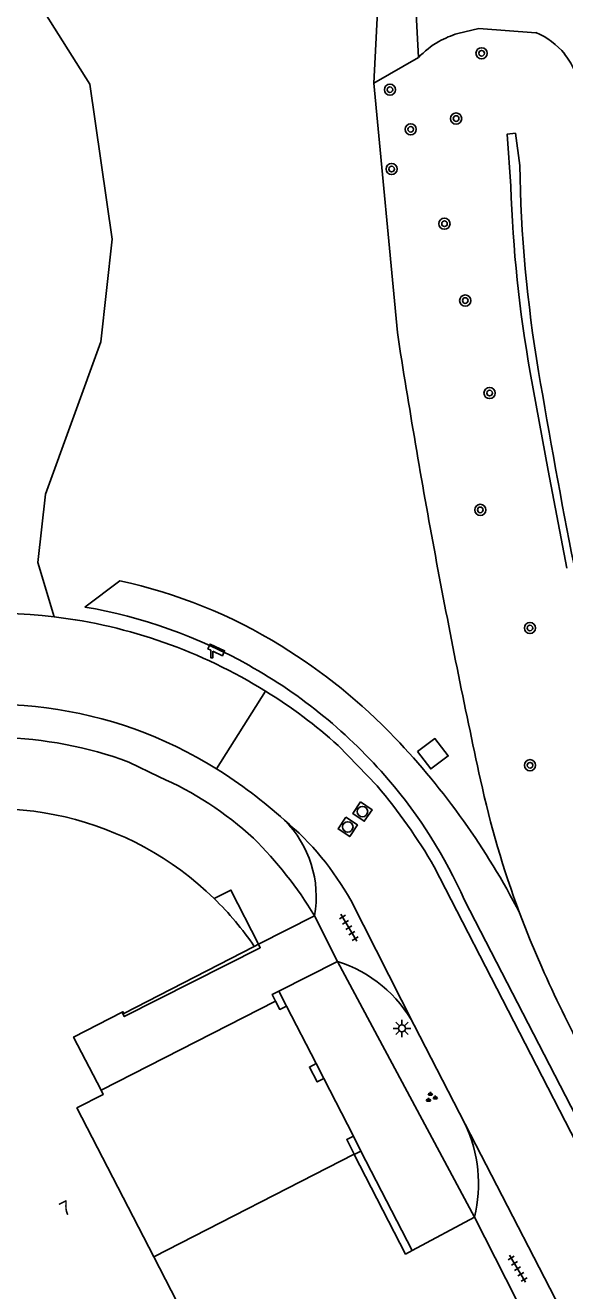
# Model space of a CAD drawing. Extents: x 136000 to 138005, y 398500 to 400500.
# Drawn here: x 136997.9 to 137036.5, y 398738 to 398828.7 of the extents above; entities that cross this region are included whole.
import ezdxf

# ---------------------------------------------------------------- set-up
doc = ezdxf.new("R2010")
doc.units = 0
for name, color, linetype in [('gg-afsc-muur', 7, 'Continuous'), ('gg-anno-huisnummerreeks BGT', 7, 'Continuous'), ('gg-bbg-hoofdgebouw', 7, 'Continuous'), ('gg-bbg-onder overbouw', 7, 'Continuous'), ('gg-bbg-pand overbouw', 7, 'Continuous'), ('gg-bbg-pilaar onder overbouw', 7, 'Continuous'), ('gg-bbg-pilaar pand', 7, 'Continuous'), ('gg-knt-BGT kruinlijn', 7, 'Continuous'), ('gg-knt-bovenkant onderkant talud', 7, 'Continuous'), ('gg-knt-bronhoudergrens', 7, 'Continuous'), ('gg-knt-verharding', 7, 'Continuous'), ('gg-kwrk-uitstroombak niveau min 01', 7, 'Continuous'), ('gt-grn-groengrens', 7, 'Continuous'), ('gt-grn-weggrens', 7, 'Continuous'), ('gt-symb-boom', 7, 'Continuous'), ('gt-symb-camera', 7, 'Continuous'), ('gt-symb-groenvak', 7, 'Continuous'), ('gt-symb-lichtmast', 7, 'Continuous'), ('gt-symb-rioolschacht', 7, 'Continuous'), ('gt-symb-tegel verharding', 7, 'Continuous')]:
    doc.layers.add(name, color=color, linetype=linetype)

# ---------------------------------------------------------------- blocks, each defined once
blk = doc.blocks.new('gt0-BOOM')
at = {"layer": 'gt-symb-boom'}
for radius in [0.4, 0.2]:
    blk.add_circle((0, 0), radius, dxfattribs=at)
blk = doc.blocks.new('gt0-TEG1')
at = {"layer": 'gt-symb-tegel verharding'}
for p, q in [((-1.125, 0), (1.125, 0)), ((-0.9, -0.25), (-0.9, 0.25)), ((-0.45, -0.25), (-0.45, 0.25)), ((0, -0.25), (0, 0.25)), ((0.45, -0.25), (0.45, 0.25)), ((0.9, -0.25), (0.9, 0.25))]:
    blk.add_line(p, q, dxfattribs=at)
blk = doc.blocks.new('gt0-GRVAK')
at = {"layer": 'gt-symb-groenvak'}
for p, q in [((-0.11, 0.189), (-0.228, 0.24)), ((-0.182, 0.153), (0.088, 0.153)), ((-0.091, 0.211), (-0.156, 0.322)), ((-0.047, 0.214), (-0.047, 0.393)), ((-0.004, 0.211), (0.061, 0.322)), ((0.015, 0.189), (0.133, 0.24)), ((0.262, -0.052), (0.197, 0.059)), ((0.305, -0.049), (0.305, 0.13)), ((0.349, -0.052), (0.414, 0.059)), ((-0.245, -0.228), (-0.363, -0.177)), ((-0.318, -0.264), (-0.047, -0.264)), ((-0.226, -0.206), (-0.291, -0.095)), ((-0.183, -0.203), (-0.183, -0.024)), ((-0.139, -0.206), (-0.074, -0.095)), ((-0.12, -0.228), (-0.002, -0.177)), ((0.243, -0.074), (0.125, -0.023)), ((0.17, -0.11), (0.441, -0.11)), ((0.368, -0.074), (0.486, -0.023))]:
    blk.add_line(p, q, dxfattribs=at)
blk = doc.blocks.new('gt0-LMAST')
at = {"layer": 'gt-symb-lichtmast'}
for p, q in [((-0.182, 0.173), (-0.447, 0.438)), ((-0.005, 0.246), (-0.005, 0.621)), ((0.172, 0.173), (0.437, 0.438)), ((-0.255, -0.004), (-0.63, -0.004)), ((-0.182, -0.181), (-0.447, -0.446)), ((-0.005, -0.254), (-0.005, -0.629)), ((0.437, -0.446), (0.172, -0.181)), ((0.245, -0.004), (0.62, -0.004))]:
    blk.add_line(p, q, dxfattribs=at)
blk.add_circle((-0.005, -0.004), 0.25, dxfattribs=at)
blk = doc.blocks.new('gt0-CAMERA')
at = {"layer": 'gt-symb-camera'}
for points in [[(0.067, 0.484), (0.753, 0.164), (0.916, 0.514), (-0.121, 0.999), (-0.284, 0.648), (-0.067, 0.547)], [(0.067, 0.484), (0.067, 0), (-0.067, 0), (-0.067, 0.547)]]:
    blk.add_lwpolyline(points, dxfattribs=at)
blk = doc.blocks.new('gt0-RS')
at = {"layer": 'gt-symb-rioolschacht'}
blk.add_lwpolyline([(-0.5, -0.5), (0.5, -0.5), (0.5, 0.5), (-0.5, 0.5)], close=True, dxfattribs=at)
blk.add_circle((0, 0), 0.375, dxfattribs=at)

msp = doc.modelspace()

# ---------------------------------------------------------------- linework, layer by layer
at = {"layer": 'gg-afsc-muur'}
msp.add_line((137021.939, 398748.05), (137025.611, 398740.921), dxfattribs=at)
msp.add_lwpolyline([(137025.611, 398740.921), (137025.131, 398740.674), (137021.455, 398747.811)], dxfattribs=at)
at = {"layer": 'gg-bbg-hoofdgebouw'}
for points in [[(136968.56, 398764.979), (136987.223, 398706.395), (137006.988, 398716.651), (137004.752, 398721.018), (137014.536, 398726.052), (137007.117, 398740.483)], [(137003.341, 398752.402), (137001.38, 398756.204), (137004.846, 398757.992)]]:
    msp.add_lwpolyline(points, dxfattribs=at)
msp.add_arc((136995.635, 398749.945), 22.615, 45.69011, 108.05217, dxfattribs=at)
at = {"layer": 'gg-bbg-onder overbouw'}
for points in [[(137014.306, 398762.703), (137004.973, 398757.889), (137004.904, 398758.022), (137004.846, 398757.992)], [(137003.341, 398752.402), (137003.497, 398752.1), (137001.623, 398751.133), (137007.117, 398740.483)]]:
    msp.add_lwpolyline(points, dxfattribs=at)
msp.add_arc((136995.597, 398749.918), 22.66, 34.34828, 45.66984, dxfattribs=at)
at = {"layer": 'gg-bbg-pand overbouw'}
for p, q in [((137015.829, 398758.772), (137003.341, 398752.402)), ((137018.735, 398754.306), (137016.611, 398758.433)), ((137021.41, 398749.122), (137019.284, 398753.244)), ((137007.117, 398740.483), (137021.444, 398747.834))]:
    msp.add_line(p, q, dxfattribs=at)
for points in [[(137014.607, 398762.857), (137012.635, 398766.738), (137011.432, 398766.127)], [(137004.846, 398757.992), (137005.004, 398757.68), (137014.735, 398762.605), (137014.607, 398762.857)]]:
    msp.add_lwpolyline(points, dxfattribs=at)
at = {"layer": 'gg-bbg-pilaar onder overbouw'}
for points in [[(137015.829, 398758.772), (137016.131, 398758.186), (137016.611, 398758.433)], [(137018.735, 398754.306), (137018.253, 398754.062), (137018.804, 398752.996), (137019.284, 398753.244)], [(137021.41, 398749.122), (137020.924, 398748.887), (137021.444, 398747.834)]]:
    msp.add_lwpolyline(points, dxfattribs=at)
at = {"layer": 'gg-bbg-pilaar pand'}
for p, q in [((137016.611, 398758.433), (137016.063, 398759.496)), ((137018.735, 398754.306), (137019.284, 398753.244)), ((137021.41, 398749.122), (137021.939, 398748.05)), ((137021.455, 398747.811), (137021.444, 398747.834)), ((137021.939, 398748.05), (137021.455, 398747.811))]:
    msp.add_line(p, q, dxfattribs=at)
msp.add_lwpolyline([(137016.063, 398759.496), (137015.581, 398759.252), (137015.829, 398758.772)], dxfattribs=at)
at = {"layer": 'gg-knt-BGT kruinlijn'}
for points in [[(137032.655, 398817.139), (137032.383, 398820.861), (137032.989, 398820.928), (137033.303, 398818.626)], [(137036.664, 398789.786), (137035.322, 398796.782), (137034.047, 398803.792)], [(137029.337, 398766.019), (137043.793, 398737.993), (137057.877, 398710.966), (137071.631, 398683.63)]]:
    msp.add_lwpolyline(points, dxfattribs=at)
for centre, radius, start, end in [((137130.802, 398820.03), 97.51, 180.82521, 189.53493), ((137127.198, 398820.253), 94.595, 181.88656, 190.02149), ((137516.558, 398884.791), 488.663, 189.53097, 191.18482), ((136995.857, 398750.628), 36.922, 60.73536, 80.14094), ((136995.859, 398750.636), 36.914, 40.53606, 60.73128), ((136997.198, 398751.781), 35.152, 23.89445, 40.53655)]:
    msp.add_arc(centre, radius, start, end, dxfattribs=at)
at = {"layer": 'gg-knt-bovenkant onderkant talud'}
for p, q in [((137026.043, 398826.341), (137022.847, 398824.523)), ((137024.541, 398806.655), (137022.847, 398824.523)), ((137002.179, 398787.004), (137004.681, 398788.872))]:
    msp.add_line(p, q, dxfattribs=at)
for points in [[(137022.847, 398824.523), (137023.212, 398831.527), (137024.08, 398843.711)], [(137026.519, 398842.825), (137025.983, 398838.091), (137025.748, 398832.193), (137026.043, 398826.341)], [(137034.446, 398828.13), (137030.376, 398828.42), (137028.856, 398828.068)], [(137033.276, 398765.118), (137034.042, 398763.155), (137034.867, 398761.216)]]:
    msp.add_lwpolyline(points, dxfattribs=at)
for centre, radius, start, end in [((137030.653, 398821.979), 6.349, 106.43898, 119.69118), ((137032.538, 398823.417), 5.085, 38.67224, 67.96233), ((137030.632, 398822.017), 6.306, 119.70283, 136.70484), ((137032.541, 398823.42), 5.08, 15.138, 38.66019), ((137562.452, 398889.996), 544.329, 188.80703, 190.51098), ((137560.975, 398889.672), 542.818, 190.50588, 192.23473), ((136997.06, 398753.234), 36.444, 58.26487, 77.92886), ((136994.5, 398749.087), 41.317, 43.68248, 58.27126), ((136985.411, 398740.484), 53.832, 27.23301, 43.62274), ((137098.085, 398789.277), 69.165, 192.21756, 200.44421), ((137126.671, 398801.945), 100.434, 203.92448, 211.81879)]:
    msp.add_arc(centre, radius, start, end, dxfattribs=at)
at = {"layer": 'gg-knt-bronhoudergrens'}
msp.add_line((136999.37, 398795.076), (137003.339, 398805.99), dxfattribs=at)
for points in [[(137003.339, 398805.99), (137004.132, 398813.332), (137002.545, 398824.445), (136996.79, 398833.573), (136985.281, 398837.938)], [(136999.37, 398795.076), (136998.821, 398790.184), (137000, 398786.302)]]:
    msp.add_lwpolyline(points, dxfattribs=at)
at = {"layer": 'gg-knt-verharding'}
for p, q in [((137023.092, 398774.194), (137020.306, 398777.093)), ((137070.909, 398683.231), (137027.184, 398768.397)), ((137025.749, 398757.073), (137021.205, 398766.003)), ((137018.609, 398764.899), (137014.607, 398762.857)), ((137018.609, 398764.899), (137020.255, 398761.619)), ((137014.607, 398762.857), (137014.306, 398762.703)), ((137020.255, 398761.619), (137016.063, 398759.496)), ((137025.749, 398757.073), (137029.388, 398749.975)), ((137030.064, 398743.321), (137025.611, 398740.921)), ((137030.064, 398743.321), (137039.194, 398725.324))]:
    msp.add_line(p, q, dxfattribs=at)
msp.add_lwpolyline([(137029.388, 398749.975), (137046.032, 398717.701), (137058.889, 398692.554)], dxfattribs=at)
for centre, radius, start, end in [((136995.513, 398749.418), 37.156, 83.06459, 104.34748), ((136995.513, 398749.42), 37.154, 58.17694, 83.06328), ((136995.552, 398749.462), 37.097, 48.14349, 58.19429), ((136995.539, 398749.766), 30.268, 57.96438, 107.19142), ((136992.515, 398745.172), 35.768, 47.98048, 57.76109), ((136992.107, 398747.98), 40.586, 30.20262, 40.23257), ((137011.04, 398766.28), 7.694, 349.65921, 45.24605), ((137003.449, 398756.152), 20.305, 29.02097, 50.16281), ((137017.486, 398752.68), 9.358, 27.99753, 72.79049), ((137020.209, 398745.681), 10.134, 346.53268, 25.06922)]:
    msp.add_arc(centre, radius, start, end, dxfattribs=at)
at = {"layer": 'gg-kwrk-uitstroombak niveau min 01'}
msp.add_lwpolyline([(137025.977, 398776.654), (137026.93, 398775.417), (137028.186, 398776.347), (137027.228, 398777.585), (137025.977, 398776.654)], dxfattribs=at)
at = {"layer": 'gt-grn-groengrens'}
for p, q in [((137005.322, 398775.906), (137007.501, 398774.839)), ((137020.255, 398761.619), (137030.064, 398743.321))]:
    msp.add_line(p, q, dxfattribs=at)
for centre, radius, start, end in [((136995.574, 398749.684), 27.975, 69.60699, 88.87936), ((136997.774, 398752.52), 24.347, 47.42938, 66.45064), ((136994.013, 398750.05), 28.731, 31.12044, 45.23867)]:
    msp.add_arc(centre, radius, start, end, dxfattribs=at)
at = {"layer": 'gt-grn-weggrens'}
msp.add_line((137011.595, 398775.425), (137015.104, 398780.989), dxfattribs=at)

# ---------------------------------------------------------------- block references
at = {"layer": 'gt-symb-boom'}
for p in [(137030.565, 398826.654), (137024.01, 398824.047), (137025.496, 398821.21), (137028.744, 398821.98), (137024.128, 398818.365), (137027.911, 398814.449), (137029.396, 398808.947), (137031.137, 398802.325), (137030.473, 398793.958), (137034.023, 398785.501), (137034.03, 398775.674)]:
    msp.add_blockref('gt0-BOOM', p, dxfattribs=at)
at = {"layer": 'gt-symb-camera'}
msp.add_blockref('gt0-CAMERA', (137011.269, 398783.356), dxfattribs=at)
at = {"layer": 'gt-symb-groenvak'}
msp.add_blockref('gt0-GRVAK', (137026.949, 398751.886), dxfattribs=at)
at = {"layer": 'gt-symb-lichtmast'}
msp.add_blockref('gt0-LMAST', (137024.875, 398756.835), dxfattribs=at)
at = {"layer": 'gt-symb-rioolschacht'}
for p, rotation in [((137022.043, 398772.357), -124.11906284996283), ((137020.994, 398771.256), -123.16559931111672)]:
    msp.add_blockref('gt0-RS', p, dxfattribs=dict(at, rotation=rotation))
at = {"layer": 'gt-symb-tegel verharding'}
for p, rotation in [((137021.064, 398764.038), 120.66892664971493), ((137033.141, 398739.622), 120.66892665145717)]:
    msp.add_blockref('gt0-TEG1', p, dxfattribs=dict(at, rotation=rotation))

# ---------------------------------------------------------------- texts
at = {"layer": 'gg-anno-huisnummerreeks BGT'}
msp.add_text('7', height=1, rotation=27.3, dxfattribs=at).set_placement((137000.699, 398743.352))

doc.saveas('drawing.dxf')
